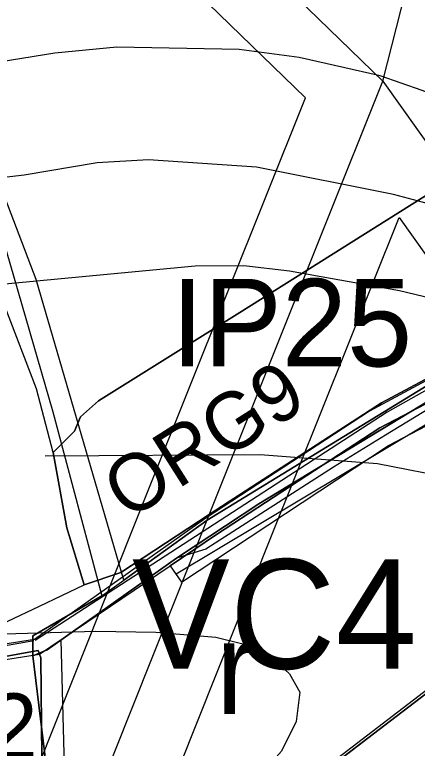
# Model space of a CAD drawing. Extents: x -1900516 to -575031, y -3809306 to -1157387.
# Drawn here: x -578770.8 to -578678.9, y -1159250.9 to -1159083.3 of the extents above; entities that cross this region are included whole.
import ezdxf

# ---------------------------------------------------------------- set-up
doc = ezdxf.new("R2010")
doc.units = 0
for name, color, linetype in [('01_OBVOD NEŘEŠENÉ', 7, 'Continuous'), ('01_OBVOD PÚ', 7, 'Continuous'), ('01_PARCELY_NÁVRH_PC', 7, 'Continuous'), ('01_PARCELY_NÁVRH_ŽP', 7, 'Continuous'), ('01_VRSTEVNICE', 7, 'Continuous'), ('02_KULTURY STAV', 7, 'Continuous'), ('03_PC_NÁVRH', 7, 'Continuous'), ('03_PC_OBJEKTY_NÁVRH', 7, 'Continuous'), ('03_PC_POPIS_STAV', 7, 'Continuous'), ('03_PC_STAV', 7, 'Continuous'), ('04_ZPF_OP_ORGAN', 7, 'Continuous'), ('06_ÚSES_IP', 7, 'Continuous'), ('07_ELEKTRO', 7, 'Continuous'), ('07_OCH_P A POPISY TI', 7, 'Continuous')]:
    doc.layers.add(name, color=color, linetype=linetype)

msp = doc.modelspace()

# ---------------------------------------------------------------- linework, layer by layer
at = {"layer": '01_OBVOD NEŘEŠENÉ'}
msp.add_line((-578668.88, -1159232.29), (-578714.38, -1159267.1), dxfattribs=at)
at = {"layer": '01_OBVOD PÚ'}
msp.add_lwpolyline([(-578580.42, -1159264.17), (-578593.74, -1159242.41), (-578597.97, -1159234.37), (-578600.72, -1159226.19), (-578607, -1159202.63), (-578613.53, -1159190.94), (-578661.89, -1159241.93), (-578668.88, -1159232.29), (-578714.38, -1159267.1)], dxfattribs=at)
at = {"layer": '01_PARCELY_NÁVRH_PC'}
for points in [[(-578817.98, -1159237.69), (-578765.18, -1159229.36), (-578724.73, -1159202.07), (-578687.51, -1159177.71), (-578649.12, -1159157.67), (-578647.01, -1159156.57), (-578636.34, -1159151.31), (-578631.96, -1159150.55), (-578627.36, -1159151.81), (-578624.02, -1159154.75), (-578622.74, -1159158.22), (-578614.1, -1159176.09), (-578606.56, -1159194.32), (-578600.93, -1159212.05), (-578603.8, -1159212.93), (-578602.93, -1159215.78), (-578600.06, -1159214.9), (-578593.2, -1159236.45), (-578586.7, -1159251.45)], [(-578652.21, -1159153.63), (-578689.84, -1159173.85), (-578727.19, -1159198.31), (-578766.32, -1159226.06), (-578842.18, -1159237.98)]]:
    msp.add_lwpolyline(points, dxfattribs=at)
at = {"layer": '01_PARCELY_NÁVRH_ŽP'}
msp.add_lwpolyline([(-578735.31, -1159209.21), (-578732.79, -1159212.94), (-578685.49, -1159181.73), (-578647.11, -1159161.74), (-578649.12, -1159157.67), (-578687.51, -1159177.71), (-578724.73, -1159202.07)], close=True, dxfattribs=at)
at = {"layer": '01_VRSTEVNICE'}
for points in [[(-578491.96, -1159264.67), (-578481.33, -1159242.29), (-578479.1, -1159235.58), (-578478.96, -1159231.11), (-578480.08, -1159226.64), (-578482.45, -1159222.16), (-578486.41, -1159217.81), (-578490.28, -1159215.17), (-578508.74, -1159205.38), (-578518.67, -1159199.23), (-578533.07, -1159186.79), (-578551.1, -1159166.51), (-578561.59, -1159157.84), (-578577.25, -1159147.92), (-578598.5, -1159135.33), (-578621.99, -1159122.89), (-578657.23, -1159108.21), (-578677.78, -1159100.66), (-578687.43, -1159097.3), (-578705.89, -1159093.11), (-578719.59, -1159091.29), (-578747.55, -1159090.73), (-578761.67, -1159092.13), (-578796.63, -1159097.72)], [(-578507.2, -1159254.32), (-578507.9, -1159245.37), (-578511.81, -1159234.19), (-578518.39, -1159223), (-578528.59, -1159211.26), (-578545.51, -1159196.57), (-578564.39, -1159178.82), (-578576.13, -1159170.15), (-578601.58, -1159154.91), (-578617.24, -1159147.5), (-578642.69, -1159137.01), (-578658.91, -1159131.28), (-578670.65, -1159128.06), (-578684.35, -1159124.43), (-578715.67, -1159118.13), (-578740.28, -1159116.46), (-578752.03, -1159117.16), (-578768.67, -1159119.95), (-578789.08, -1159122.33)], [(-578638.35, -1159161.34), (-578649.4, -1159156.3), (-578666.18, -1159150.43), (-578682.95, -1159146.38), (-578708.12, -1159141.9), (-578718.54, -1159140.72), (-578729.66, -1159140.78), (-578780.41, -1159145.54)], [(-578639.47, -1159200.35), (-578657.79, -1159193.36), (-578670.09, -1159189.44), (-578687.99, -1159185.95), (-578714.83, -1159183.85), (-578763.91, -1159184.13)], [(-578775.8, -1159224.82), (-578752.31, -1159224.12), (-578738.6, -1159224.4), (-578724.9, -1159225.52), (-578719.03, -1159226.92), (-578712.46, -1159229.85), (-578708.12, -1159233.91), (-578705.75, -1159238.1), (-578706.58, -1159244.81), (-578709.94, -1159251.52), (-578718.19, -1159260.89), (-578751.47, -1159287.18), (-578762.09, -1159298.78), (-578771.18, -1159312.21)]]:
    msp.add_lwpolyline(points, dxfattribs=at)
at = {"layer": '02_KULTURY STAV'}
for points in [[(-578574.68, -1159052.93), (-578611.17, -1159089.26), (-578632.65, -1159109.54), (-578649.76, -1159125.08), (-578643.29, -1159133.51), (-578654.77, -1159144.71), (-578648.75, -1159152.41), (-578653.27, -1159153.89), (-578654.54, -1159154.47), (-578716.11, -1159192.14), (-578726.86, -1159198.82), (-578745.95, -1159212.49), (-578765.93, -1159143.8), (-578789.9, -1159081.01)], [(-578775.53, -1159127.99), (-578762.13, -1159174.04), (-578750.96, -1159216.07), (-578766.69, -1159225.18), (-578766.71, -1159229.78), (-578760.56, -1159280.49), (-578764.01, -1159319.64), (-578759.09, -1159323.9), (-578770.49, -1159346.44), (-578756.67, -1159332.47), (-578743.67, -1159350.53), (-578721.83, -1159377.56), (-578715.38, -1159387.23), (-578698.9, -1159404.24), (-578689.48, -1159412.63), (-578672.99, -1159428.98), (-578666.41, -1159437.22), (-578675.25, -1159435.03), (-578693.15, -1159431.1), (-578739.9, -1159419.59), (-578781.83, -1159408.23)], [(-578775.53, -1159127.99), (-578762.13, -1159174.04), (-578750.96, -1159216.07), (-578766.69, -1159225.18), (-578766.71, -1159229.78), (-578760.56, -1159280.49), (-578764.01, -1159319.64), (-578759.09, -1159323.9), (-578770.49, -1159346.44), (-578756.67, -1159332.47), (-578743.67, -1159350.53), (-578721.83, -1159377.56), (-578715.38, -1159387.23), (-578698.9, -1159404.24), (-578689.48, -1159412.63), (-578672.99, -1159428.98), (-578666.41, -1159437.22), (-578675.25, -1159435.03), (-578693.15, -1159431.1), (-578739.9, -1159419.59), (-578781.83, -1159408.23)], [(-578653, -1159157.37), (-578715.08, -1159195.09), (-578733.89, -1159207.49), (-578763.42, -1159228.38), (-578766.71, -1159229.78), (-578766.69, -1159225.18), (-578750.96, -1159216.07), (-578745.95, -1159212.49), (-578726.86, -1159198.82), (-578716.11, -1159192.14), (-578654.54, -1159154.47)], [(-578714.38, -1159267.1), (-578668.88, -1159232.29), (-578661.89, -1159241.93), (-578613.53, -1159190.94), (-578607, -1159202.63), (-578600.72, -1159226.19), (-578597.97, -1159234.37), (-578593.74, -1159242.41), (-578580.42, -1159264.17)]]:
    msp.add_lwpolyline(points, dxfattribs=at)
for points in [[(-578750.96, -1159216.07), (-578745.95, -1159212.49), (-578765.93, -1159143.8), (-578789.9, -1159081.01), (-578779.34, -1159073.2), (-578780.39, -1159072.12), (-578785.57, -1159075.82), (-578792.92, -1159081.42), (-578775.53, -1159127.99), (-578762.13, -1159174.04)], [(-578766.71, -1159229.78), (-578763.42, -1159228.38), (-578733.89, -1159207.49), (-578715.08, -1159195.09), (-578653, -1159157.37), (-578638.41, -1159150.57), (-578637, -1159150.48), (-578635.43, -1159150.96), (-578630.61, -1159154.28), (-578617.55, -1159183.19), (-578630.4, -1159197.76), (-578650.95, -1159216.74), (-578668.88, -1159232.29), (-578714.38, -1159267.1), (-578729.84, -1159278.37), (-578744.59, -1159293.5), (-578764.01, -1159319.64), (-578760.56, -1159280.49)]]:
    msp.add_lwpolyline(points, close=True, dxfattribs=at)
at = {"layer": '03_PC_NÁVRH'}
msp.add_lwpolyline([(-579031.28, -1159351.27), (-578876.06, -1159264.94), (-578841.47, -1159239.63), (-578766.48, -1159226.28)], dxfattribs=at)
at = {"layer": '03_PC_STAV'}
msp.add_lwpolyline([(-578624.68, -1159150.95), (-578630.46, -1159148.75), (-578636.08, -1159149.06), (-578652.03, -1159155.09), (-578685.77, -1159174.11), (-578766.16, -1159226.27)], dxfattribs=at)
at = {"layer": '04_ZPF_OP_ORGAN'}
msp.add_line((-578758.9, -1159200.51), (-578755.01, -1159213.54), dxfattribs=at)
for points in [[(-578762.04, -1159183.36), (-578765.87, -1159168.76), (-578773.07, -1159149.94), (-578793.65, -1159089.25), (-578795.58, -1159079.34), (-578795.27, -1159075.99), (-578791.37, -1159071.9), (-578791.69, -1159068.99), (-578805.61, -1158990.49), (-578808.68, -1158974.26), (-578809.14, -1158971.01), (-578808.11, -1158968.03), (-578813.28, -1158970.34), (-578834.9, -1158979.44), (-578865.04, -1158997.83), (-578830.76, -1159080.15), (-578795.77, -1159174.05), (-578789.1, -1159194.41), (-578781, -1159219.07), (-578782.87, -1159226.66), (-578779.45, -1159225.94), (-578775.36, -1159223.24), (-578765.19, -1159218.39), (-578755.01, -1159213.54)], [(-578830.76, -1159080.15), (-578795.77, -1159174.05), (-578789.1, -1159194.41), (-578781, -1159219.07), (-578782.87, -1159226.66), (-578779.45, -1159225.94), (-578775.36, -1159223.24), (-578765.19, -1159218.39), (-578755.01, -1159213.54), (-578758.9, -1159200.51), (-578762.04, -1159183.36), (-578765.87, -1159168.76), (-578773.07, -1159149.94), (-578793.65, -1159089.25), (-578795.58, -1159079.34)], [(-578755.01, -1159213.54), (-578746.62, -1159210.7), (-578726.24, -1159197.37), (-578687.07, -1159171.97), (-578653.27, -1159153.89), (-578672.71, -1159121.97), (-578719.4, -1159151.33), (-578751.72, -1159171.52), (-578755.79, -1159175.17), (-578757.21, -1159178.44), (-578762.04, -1159183.36), (-578758.9, -1159200.51)], [(-578760.32, -1159226.23), (-578758.7, -1159286.69), (-578759.89, -1159310.24), (-578729.96, -1159278.24), (-578669.39, -1159231.85), (-578650.95, -1159216.74), (-578614, -1159183.11), (-578629.51, -1159154.84), (-578632.88, -1159150.35), (-578640.82, -1159152.26), (-578655.64, -1159160.69), (-578674.28, -1159172.13), (-578686.18, -1159179.4), (-578698.07, -1159186.66), (-578727.21, -1159205.44), (-578733.89, -1159207.49), (-578760.32, -1159226.23)], [(-578755.01, -1159213.54), (-578758.9, -1159200.51), (-578762.04, -1159183.36)], [(-578800.51, -1159234.88), (-578765.47, -1159228.57), (-578764.86, -1159230.26), (-578764.63, -1159252.94), (-578763.42, -1159263.52), (-578763.35, -1159298.61), (-578764.11, -1159314.38), (-578768.45, -1159322.3), (-578772.95, -1159339.22), (-578756.15, -1159346.72), (-578746.4, -1159354.66), (-578737.28, -1159370.38), (-578729.9, -1159382.19), (-578721.38, -1159392.19), (-578684.84, -1159427.38), (-578680.61, -1159430.7), (-578817.23, -1159394.73)], [(-578817.23, -1159394.73), (-578680.61, -1159430.7), (-578684.84, -1159427.38), (-578721.38, -1159392.19), (-578729.9, -1159382.19), (-578737.28, -1159370.38), (-578746.4, -1159354.66), (-578756.15, -1159346.72), (-578772.95, -1159339.22), (-578768.45, -1159322.3), (-578764.11, -1159314.38), (-578763.35, -1159298.61), (-578763.42, -1159263.52), (-578764.63, -1159252.94), (-578764.86, -1159230.26), (-578765.47, -1159228.57), (-578800.51, -1159234.88)]]:
    msp.add_lwpolyline(points, dxfattribs=at)
for points in [[(-578762.04, -1159183.36), (-578757.21, -1159178.44), (-578755.79, -1159175.17), (-578751.72, -1159171.52), (-578719.4, -1159151.33), (-578672.71, -1159121.97), (-578653.27, -1159153.89), (-578687.07, -1159171.97), (-578726.24, -1159197.37), (-578746.62, -1159210.7), (-578755.01, -1159213.54), (-578758.9, -1159200.51)], [(-578760.32, -1159226.23), (-578758.7, -1159286.69), (-578759.89, -1159310.24), (-578729.96, -1159278.24), (-578669.39, -1159231.85), (-578650.95, -1159216.74), (-578614, -1159183.11), (-578629.51, -1159154.84), (-578632.88, -1159150.35), (-578640.82, -1159152.26), (-578655.64, -1159160.69), (-578674.28, -1159172.13), (-578686.18, -1159179.4), (-578698.07, -1159186.66), (-578727.21, -1159205.44), (-578733.89, -1159207.49)]]:
    msp.add_lwpolyline(points, close=True, dxfattribs=at)
at = {"layer": '06_ÚSES_IP'}
msp.add_lwpolyline([(-578733.99, -1159211.03), (-578648.12, -1159159.65)], dxfattribs=at)
at = {"layer": '07_ELEKTRO'}
for points in [[(-578878.16, -1158909.99), (-578860.06, -1158928.47), (-578841.67, -1158945.72), (-578794.56, -1158992.9), (-578740.72, -1159046.14), (-578686.82, -1159098.53)], [(-578686.82, -1159098.53), (-578655.63, -1158975.82)], [(-579151.64, -1160263.33), (-579124.46, -1160194.57), (-579087.04, -1160099.75), (-579049.34, -1160005.38), (-579007.3, -1159900.49), (-578960.77, -1159784.26), (-578916.42, -1159673.56), (-578883.23, -1159588.77), (-578839.91, -1159480.62), (-578797.65, -1159374.86), (-578761.31, -1159285.02), (-578726.29, -1159197.17), (-578686.82, -1159098.53)], [(-578686.82, -1159098.53), (-578650.07, -1159150.16), (-578604.21, -1159175.88), (-578542.57, -1159210.7), (-578476.38, -1159248.19), (-578429.96, -1159274.75), (-578393.45, -1159295.29)]]:
    msp.add_lwpolyline(points, dxfattribs=at)
at = {"layer": '07_OCH_P A POPISY TI'}
for p, q in [((-578740.22, -1159191.61), (-578704.48, -1159102.28)), ((-578712.36, -1159202.73), (-578683.1, -1159129.62)), ((-578775.23, -1159279.43), (-578740.22, -1159191.61)), ((-578747.39, -1159290.61), (-578712.36, -1159202.73))]:
    msp.add_line(p, q, dxfattribs=at)
for points in [[(-578892.5, -1158916.78), (-578870.55, -1158939.19), (-578852.11, -1158956.49), (-578805.14, -1159003.53), (-578751.22, -1159056.85), (-578704.48, -1159102.28)], [(-578683.1, -1159129.62), (-578660.34, -1159161.6), (-578611.57, -1159188.95), (-578549.96, -1159223.76), (-578483.8, -1159261.23), (-578437.36, -1159287.8), (-578400.8, -1159308.36)]]:
    msp.add_lwpolyline(points, dxfattribs=at)

# ---------------------------------------------------------------- texts
at = {"layer": '02_KULTURY STAV'}
msp.add_text('r', height=21, dxfattribs=at).set_placement((-578724.93, -1159243.05))
msp.add_text('r', height=21, dxfattribs=at).set_placement((-578724.93, -1159243.05))
at = {"layer": '03_PC_OBJEKTY_NÁVRH'}
msp.add_text('B2', height=15, dxfattribs=at).set_placement((-578790.13, -1159253.37))
at = {"layer": '03_PC_POPIS_STAV'}
msp.add_text('VC4B', height=25, dxfattribs=at).set_placement((-578744.04, -1159232.72))
at = {"layer": '04_ZPF_OP_ORGAN'}
msp.add_text('ORG9', height=13, rotation=32.3853, dxfattribs=at).set_placement((-578745.07, -1159199.05))
at = {"layer": '06_ÚSES_IP'}
msp.add_text('IP25', height=20, dxfattribs=at).set_placement((-578735.11, -1159163.66))

doc.saveas('drawing.dxf')
